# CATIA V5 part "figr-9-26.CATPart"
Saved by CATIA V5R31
Part number: Part1
Bounding box of the stored display mesh (mm): x -75 to 75, y -50 to 50, z 0 to 40
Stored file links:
  D:\PROJECTS\Project 2021\US EDITION\CATIA V5 6R 2021\Resources\Part Files\c09_catia_v5_6r2021_prt\c09_catia_v5_6r2021_prt\figr-9-26.CATPart
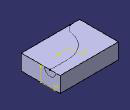
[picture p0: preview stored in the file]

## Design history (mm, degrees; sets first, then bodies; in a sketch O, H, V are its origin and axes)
Body1 (main body)
  Sketch1 on xy-plane, origin (0, 0, 0), H (1, 0, 0), V (0, 1, 0)
    line L1 (-75, 50) -> (75, 50)
    line L2 (75, 50) -> (75, -50)
    line L3 (75, -50) -> (-75, -50)
    line L4 (-75, -50) -> (-75, 50)
    axis line L5 (75, -50) -> (-75, 50)
    length L2 = 100
    length L3 = 150
    horizontal: L1 H, L3 H
    vertical: L2 V, L4 V
    midpoint: O L5
  Pad1: profile Sketch1, direction (0, 0, 1), length 40
  Sketch2 on face of Pad1, origin (75, 0, 0), H (0, 1, 0), V (0, 0, 1)
    arc A1 centre (24.1478, 40) radius 14.6047 from (9.543, 40) to (38.7525, 40) ccw
    point P1 (24.1478, 40)
    reference projected point E1 (24.1478, 40) from vertex of Sketch3
    line L1 (9.543, 40) -> (38.7525, 40)
    coincidence: P1 E1
    horizontal: L1 H
  Sketch3 on face of Pad1, origin (0, 0, 40), H (1, 0, 0), V (0, 1, 0)
    point P1 (75, 24.1478)
    line L1 (75, 24.1478) -> (28.6577, 24.1478)
    arc A1 centre (28.6577, -39.2062) radius 63.354 from (28.6577, 24.1478) to (-33.8383, -28.8149) ccw
    arc A2 centre (-62.192, -24.1005) radius 28.7429 from (-33.8383, -28.8149) to (-49.7271, -50) cw
    point P6 (-49.7271, -50)
    reference projected line E1 (75, -50) -> (75, 50) from edge [face of Pad1 | face of Pad1]
    reference projected line E2 (-75, -50) -> (75, -50) from edge [face of Pad1 | face of Pad1]
    horizontal: L1 H
    tangency: A1 L1, A2 A1
    coincidence: P1 E1, P6 E2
